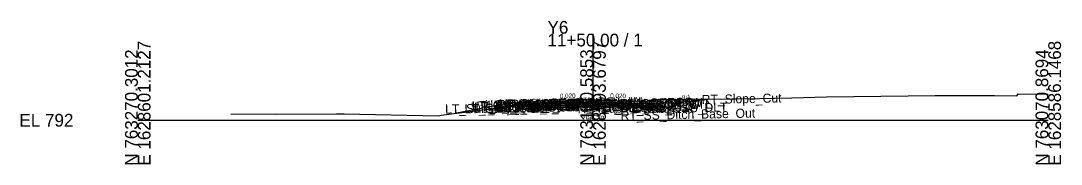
# Model space of a CAD drawing. Extents: x -26 to 203, y -10 to 6017.
# Drawn here: x -25.7 to 202.8, y 2990.3 to 3021.9 of the extents above; entities that cross this region are included whole.
import ezdxf

# ---------------------------------------------------------------- set-up
doc = ezdxf.new("R2010")
doc.units = 0
for name, color, linetype in [('Default', 7, 'Continuous'), ('Exist Cross Section Cell', 7, 'Continuous'), ('Exist XS Center Line Elevation Label', 7, 'Continuous'), ('Exist XS Ground Line', 7, 'Continuous'), ('Prop CMT Concrete Structures', 7, 'Continuous'), ('Prop CMT Pvmt Course 1', 7, 'Continuous'), ('Prop CMT Pvmt Course 2', 7, 'Continuous'), ('Prop CMT Pvmt Course 3', 7, 'Continuous'), ('Prop CMT Pvmt Surface', 7, 'Continuous'), ('Prop CMT Pvmt Surface Shoulder', 7, 'Continuous'), ('Prop CMT Pvmt Wedge Surface 1', 7, 'Continuous'), ('Prop CMT Pvmt Wedge Surface 2', 7, 'Continuous'), ('Prop CMT Pvmt Wedge Surface 3', 7, 'Continuous'), ('Prop CMT Shld Paved Course 1', 7, 'Continuous'), ('Prop CMT Shld Paved Course 2', 7, 'Continuous'), ('Prop CMT Shld Paved Course 3', 7, 'Continuous'), ('Prop CMT Slope Grass', 7, 'Continuous'), ('Prop CMT Subgrade Earthwork', 7, 'Continuous'), ('Prop XS SE Text', 7, 'Continuous'), ('Prop XS Side Slope Text', 7, 'Continuous'), ('Scratch_Level_0', 7, 'Continuous')]:
    doc.layers.add(name, color=color, linetype=linetype)

msp = doc.modelspace()

# ---------------------------------------------------------------- linework, layer by layer
at = {"layer": 'Exist Cross Section Cell'}
for p, q in [((100, 3000), (100, 3019.06)), ((0, 3000), (100, 3000)), ((100, 3000), (200, 3000))]:
    msp.add_line(p, q, dxfattribs=at)
at = {"layer": 'Exist XS Ground Line'}
msp.add_lwpolyline([(20.45, 3001.42), (30.33, 3001.37), (43.64, 3001.4), (44.17, 3001.41), (44.5, 3001.41), (45.31, 3001.4), (66.06, 3000.99), (66.68, 3001.08), (84.34, 3003.38), (89.44, 3003.99), (94.91, 3004.38), (100.2, 3004.6), (100.87, 3004.41), (104.76, 3004.32), (111.05, 3004.22), (115.54, 3004.54), (121.42, 3004.67), (130.41, 3004.68), (131.75, 3004.72), (136.59, 3004.77), (139.83, 3004.83), (143.7, 3004.91), (151.27, 3005.17), (169.25, 3005.4), (175.09, 3005.42), (188.18, 3005.42), (193.06, 3005.39), (193.38, 3005.79), (200, 3005.72)], dxfattribs=at)
at = {"layer": 'Prop CMT Concrete Structures'}
for p, q in [((87, 3003.76), (82, 3003.86)), ((113, 3003.76), (118, 3003.86))]:
    msp.add_line(p, q, dxfattribs=at)
for points in [[(87, 3003.76), (87, 3003.18), (89, 3003.18)], [(89, 3003.76), (88, 3003.68), (87, 3003.76)], [(89, 3003.18), (89, 3003.76)], [(111, 3003.18), (111, 3003.76)], [(113, 3003.76), (113, 3003.18), (111, 3003.18)], [(111, 3003.76), (112, 3003.68), (113, 3003.76)]]:
    msp.add_lwpolyline(points, dxfattribs=at)
at = {"layer": 'Prop CMT Pvmt Course 1'}
for points in [[(100, 3003.98), (89, 3003.76)], [(89, 3003.76), (89, 3003.51)], [(89, 3003.51), (100, 3003.73)], [(100, 3003.98), (89.44, 3003.77)], [(100, 3003.86), (100, 3003.98)], [(100, 3003.73), (100, 3003.98)], [(100, 3003.98), (111, 3003.76)], [(100, 3003.86), (100, 3003.98)], [(100, 3003.98), (111, 3003.76)], [(100, 3003.73), (100, 3003.98)], [(111, 3003.51), (100, 3003.73)], [(111, 3003.76), (111, 3003.64)], [(111, 3003.76), (111, 3003.51)]]:
    msp.add_lwpolyline(points, dxfattribs=at)
at = {"layer": 'Prop CMT Pvmt Course 2'}
for points in [[(100, 3003.73), (89, 3003.51)], [(89, 3003.51), (89, 3003.18)], [(89, 3003.18), (100, 3003.4)], [(100, 3003.4), (100, 3003.73)], [(100, 3003.4), (100, 3003.73)], [(100, 3003.73), (111, 3003.51)], [(111, 3003.18), (100, 3003.4)], [(111, 3003.51), (111, 3003.18)]]:
    msp.add_lwpolyline(points, dxfattribs=at)
at = {"layer": 'Prop CMT Pvmt Course 3'}
msp.add_line((113, 3003.18), (113.5, 3003.18), dxfattribs=at)
for points in [[(100, 3003.4), (89, 3003.18)], [(89, 3003.18), (89, 3002.84)], [(89, 3002.84), (100, 3003.06)], [(100, 3003.06), (100, 3003.4)], [(100, 3003.4), (111, 3003.18)], [(100, 3003.06), (100, 3003.4)], [(111, 3002.84), (100, 3003.06)], [(111, 3003.18), (111, 3002.84)]]:
    msp.add_lwpolyline(points, dxfattribs=at)
at = {"layer": 'Prop CMT Pvmt Surface'}
for points in [[(100, 3003.98), (89, 3003.76)], [(100, 3003.98), (89.44, 3003.77)], [(100, 3003.98), (111, 3003.76)], [(100, 3003.98), (111, 3003.76)]]:
    msp.add_lwpolyline(points, dxfattribs=at)
at = {"layer": 'Prop CMT Pvmt Surface Shoulder'}
for points in [[(89, 3003.76), (89, 3003.76)], [(111, 3003.76), (111, 3003.76)]]:
    msp.add_lwpolyline(points, dxfattribs=at)
at = {"layer": 'Prop CMT Pvmt Wedge Surface 1'}
msp.add_lwpolyline([(111, 3003.64), (111, 3003.76)], dxfattribs=at)
at = {"layer": 'Prop CMT Pvmt Wedge Surface 2'}
for points in [[(100, 3003.73), (89.44, 3003.52)], [(100, 3003.73), (100, 3003.98)], [(100, 3003.73), (100, 3003.98)], [(100, 3003.73), (100, 3003.98)], [(100, 3003.73), (100, 3003.98)], [(100, 3003.73), (111, 3003.51)], [(111, 3003.51), (111, 3003.76)]]:
    msp.add_lwpolyline(points, dxfattribs=at)
at = {"layer": 'Prop CMT Pvmt Wedge Surface 3'}
for points in [[(100, 3003.4), (89.44, 3003.19)], [(100, 3003.4), (100, 3003.98)], [(100, 3003.4), (100, 3003.98)], [(100, 3003.4), (100, 3003.98)], [(100, 3003.4), (100, 3003.98)], [(100, 3003.4), (111, 3003.18)]]:
    msp.add_lwpolyline(points, dxfattribs=at)
at = {"layer": 'Prop CMT Shld Paved Course 1'}
for points in [[(89, 3003.76), (89, 3003.76)], [(89, 3003.51), (89, 3003.76)], [(111, 3003.76), (111, 3003.76)], [(111, 3003.51), (111, 3003.76)]]:
    msp.add_lwpolyline(points, dxfattribs=at)
at = {"layer": 'Prop CMT Shld Paved Course 2'}
for p, q in [((87, 3003.18), (89, 3003.18)), ((113, 3003.18), (111, 3003.18))]:
    msp.add_line(p, q, dxfattribs=at)
for points in [[(89, 3003.18), (89, 3003.51)], [(111, 3003.18), (111, 3003.51)]]:
    msp.add_lwpolyline(points, dxfattribs=at)
at = {"layer": 'Prop CMT Shld Paved Course 3'}
for p, q in [((86.16, 3002.84), (89, 3002.84)), ((113.84, 3002.84), (111, 3002.84))]:
    msp.add_line(p, q, dxfattribs=at)
for points in [[(89, 3003.18), (87, 3003.18), (86.5, 3003.18), (86.16, 3002.84)], [(89, 3002.84), (89, 3003.18)], [(111, 3002.84), (111, 3003.18)], [(111, 3003.18), (113.5, 3003.18), (113.5, 3003.18), (113.84, 3002.84)]]:
    msp.add_lwpolyline(points, dxfattribs=at)
at = {"layer": 'Prop CMT Slope Grass'}
for points in [[(87, 3003.76), (82, 3003.86), (70, 3001.52)], [(113, 3003.76), (118, 3003.86), (125.33, 3004.68)]]:
    msp.add_lwpolyline(points, dxfattribs=at)
at = {"layer": 'Prop CMT Subgrade Earthwork'}
for p, q in [((86.16, 3002.84), (85.2, 3003.8)), ((113.84, 3002.84), (114.8, 3003.8)), ((89, 3002.84), (86.16, 3002.84)), ((111, 3002.84), (113.84, 3002.84))]:
    msp.add_line(p, q, dxfattribs=at)
for points in [[(100, 3003.06), (89, 3002.84)], [(100, 3003.06), (111, 3002.84)]]:
    msp.add_lwpolyline(points, dxfattribs=at)

# ---------------------------------------------------------------- texts
at = {"layer": 'Default'}
msp.add_text('-', height=0.0001, dxfattribs=at).set_placement((0, 3000))
at = {"layer": 'Exist Cross Section Cell'}
for s, p in [('Y6', (90, 3019.06)), ('11+50.00 / 1', (90, 3016.26)), ('EL 792', (-26, 2998.6))]:
    msp.add_text(s, height=2.8, dxfattribs=at).set_placement(p)
for s, p in [('E 1628601.2127', (2.8, 2990)), ('E 1628593.6797', (102.8, 2990)), ('E 1628586.1468', (202.8, 2990)), ('N 763270.3012', (0, 2990)), ('N 763170.5853', (100, 2990)), ('N 763070.8694', (200, 2990))]:
    msp.add_text(s, height=2.8, rotation=90, dxfattribs=at).set_placement(p)
at = {"layer": 'Exist XS Center Line Elevation Label'}
msp.add_text('796.38', height=1.2, dxfattribs=at).set_placement((97.45, 2999.78))
at = {"layer": 'Prop XS SE Text'}
for rotation, p in [(1.1458, (92.73, 3004.84)), (358.8542, (103.77, 3004.91))]:
    msp.add_text('0.020', height=1, rotation=rotation, dxfattribs=at).set_placement(p)
at = {"layer": 'Prop XS Side Slope Text'}
for s, rotation, p in [('9:1', 6.3402, (119.59, 3004.47)), ('5.12:1', 11.0565, (73.41, 3002.82))]:
    msp.add_text(s, height=1, rotation=rotation, dxfattribs=at).set_placement(p)
at = {"layer": 'Scratch_Level_0'}
for s, p in [('RT_Slope_Cut', (123.88, 3003.57)), ('LT_Sub_OSS_DLT', (67.53, 3001.46)), ('LT_Sub_Trench_Out', (71.79, 3001.5)), ('LT_GS_OS_CTL', (73.39, 3002.15)), ('LT_PS3_Shelf_Out', (73.91, 3001.88)), ('LT_Slope_Fill', (74.24, 3002.07)), ('LT_PV2_OEEOP_W', (76.88, 3002.27)), ('LT_PV3_OEEOP_W', (76.88, 3001.94)), ('LT_PV1_OEEOP_W', (77.44, 3002.41)), ('LT_PS3_OEOP', (78.66, 3001.97)), ('LT_PS2_OEOP', (79, 3002.31)), ('LT_Sub_OEOT', (79.1, 3001.65)), ('LT_PV2_OEOT', (79.2, 3002.32)), ('LT_PV3_OEOT', (79.2, 3001.98)), ('LT_PV1_OEEOP', (79.33, 3002.57)), ('LT_PV1_OEOT', (79.76, 3002.58)), ('LT_PS1_OEOP', (79.83, 3002.58)), ('RT_PV1_PGL_W', (89.86, 3002.65)), ('LT_PV1_PGL_W', (89.91, 3002.65)), ('Sub_PGL', (93.83, 3001.94)), ('PV2_PGL', (93.93, 3002.61)), ('PV3_PGL', (93.93, 3002.28)), ('PV1_PGL', (94.49, 3002.87)), ('RT_Sub_Trench_Out', (96.62, 3001.5)), ('RT_PS3_Shelf_Out', (98.06, 3001.88)), ('RT_PV2_OEEOP_W', (98.39, 3002.26)), ('RT_PV3_OEEOP_W', (98.39, 3001.93)), ('RT_PV1_OEEOP_W', (98.96, 3002.4)), ('RT_PV1_OEEOP', (100.85, 3002.56)), ('RT_Sub_OEOT', (101.05, 3001.65)), ('RT_PV2_OEOT', (101.15, 3002.31)), ('RT_PV3_OEOT', (101.15, 3001.98)), ('RT_PS2_OEOP', (101.47, 3002.31)), ('RT_PV1_OEOT', (101.71, 3002.58)), ('RT_PS1_OEOP', (101.78, 3002.58)), ('RT_PS3_OEOP', (101.81, 3001.97)), ('RT_GS_OS_CTL', (105.34, 3002.15)), ('RT_Sub_OSS_DLT', (106.06, 3001.44)), ('RT_SS_Ditch_Base_Out', (106.06, 3000))]:
    msp.add_text(s, height=2, rotation=1.1458, dxfattribs=at).set_placement(p)

doc.saveas('drawing.dxf')
